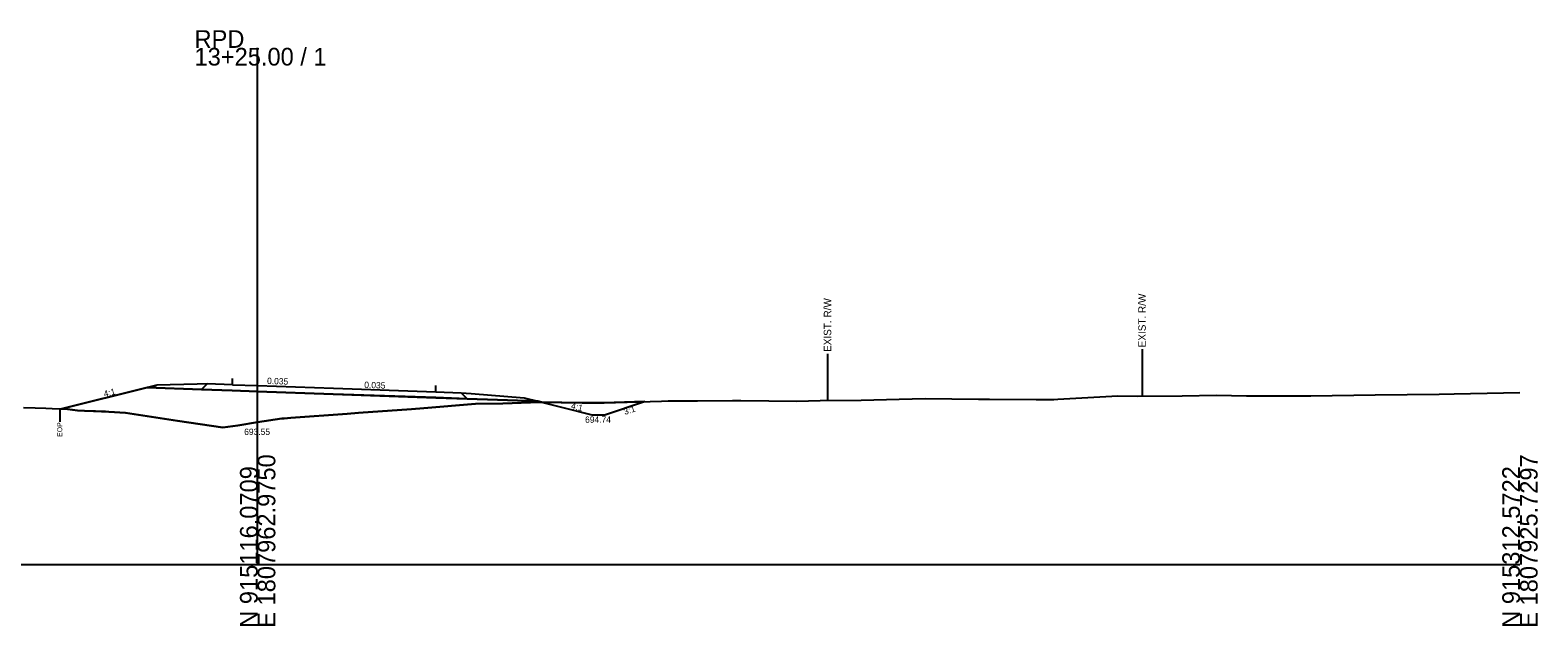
# Model space of a CAD drawing. Extents: x -26 to 403, y -10 to 8517.
# Drawn here: x 164 to 402.8, y 6490.3 to 6584.7 of the extents above; entities that cross this region are included whole.
import ezdxf

# ---------------------------------------------------------------- set-up
doc = ezdxf.new("R2010")
doc.units = 0
for name, color, linetype in [('Exist Cross Section Cell', 7, 'Continuous'), ('Exist XS Center Line Elevation Label', 7, 'Continuous'), ('Exist XS Ground Line', 7, 'Continuous'), ('Old_Level_10', 7, 'Continuous'), ('Prop XS Ditch Slope Text', 7, 'Continuous'), ('Prop XS Ditch Standard Text', 7, 'Continuous'), ('Prop XS Earthwork Shape', 7, 'Continuous'), ('Prop XS EOT Tick Mark', 7, 'Continuous'), ('Prop XS Finish Grade', 7, 'Continuous'), ('Prop XS Finish Grade Earthwork', 7, 'Continuous'), ('Prop XS Finish Grade Paved Shoulder', 7, 'Continuous'), ('Prop XS Finish Grade Pavement', 7, 'Continuous'), ('Prop XS Hydro Fill Slope Data', 7, 'Continuous'), ('Prop XS Pvmt Edge Slope', 7, 'Continuous'), ('Prop XS SE Text', 7, 'Continuous'), ('Prop XS Side Slope Text', 7, 'Continuous'), ('Prop XS Subgrade Earthwork', 7, 'Continuous')]:
    doc.layers.add(name, color=color, linetype=linetype)

msp = doc.modelspace()

# ---------------------------------------------------------------- linework, layer by layer
at = {"layer": 'Exist Cross Section Cell'}
for p, q in [((200, 6500), (200, 6581.88)), ((0, 6500), (200, 6500)), ((200, 6500), (400, 6500))]:
    msp.add_line(p, q, dxfattribs=at)
at = {"layer": 'Exist XS Ground Line'}
msp.add_lwpolyline([(162.89, 6524.9), (164.77, 6524.84), (166.43, 6524.77), (167.42, 6524.74), (168.64, 6524.7), (169.09, 6524.68), (169.85, 6524.61), (171.45, 6524.45), (172.58, 6524.39), (174.01, 6524.32), (174.32, 6524.3), (175.24, 6524.26), (175.91, 6524.24), (176.42, 6524.2), (179.08, 6524.06), (187.3, 6522.77), (194.48, 6521.72), (196.84, 6522.05), (200, 6522.55), (203.83, 6523.15), (204.18, 6523.15), (205.26, 6523.27), (214.18, 6523.91), (215.98, 6524.04), (224.36, 6524.62), (226.32, 6524.8), (234.53, 6525.48), (238.87, 6525.53), (244.71, 6525.75), (251.43, 6525.64), (254.89, 6525.64), (263.99, 6525.91), (265.07, 6525.95), (269.67, 6525.96), (275.25, 6526.03), (276.55, 6525.99), (285.42, 6525.92), (289.11, 6525.99), (295.6, 6526.07), (301.67, 6526.21), (305.78, 6526.32), (314.22, 6526.21), (315.96, 6526.21), (323.37, 6526.18), (326.14, 6526.18), (326.78, 6526.2), (336.31, 6526.75), (339.34, 6526.72), (346.49, 6526.76), (351.9, 6526.85), (356.67, 6526.77), (364.46, 6526.74), (366.85, 6526.73), (377.07, 6526.89), (387.2, 6527.01), (389.57, 6527.06), (397.38, 6527.22), (400, 6527.29)], dxfattribs=at)
at = {"layer": 'Old_Level_10'}
for p, q in [((340.13, 6534.13), (340.13, 6526.73)), ((290.29, 6533.41), (290.29, 6526)), ((168.64, 6524.7), (168.64, 6522.65))]:
    msp.add_line(p, q, dxfattribs=at)
at = {"layer": 'Prop XS Earthwork Shape'}
for points in [[(228.21, 6526.46), (233.18, 6526.29), (244.4, 6525.89), (244.99, 6525.75), (244.71, 6525.75), (238.87, 6525.53), (234.53, 6525.48), (226.32, 6524.8), (224.36, 6524.62), (215.98, 6524.04), (214.18, 6523.91), (205.26, 6523.27), (204.18, 6523.15), (203.83, 6523.15), (200, 6522.55), (196.84, 6522.05), (194.48, 6521.72), (187.3, 6522.77), (179.08, 6524.06), (176.42, 6524.2), (175.91, 6524.24), (175.24, 6524.26), (174.32, 6524.3), (174.01, 6524.32), (172.58, 6524.39), (171.45, 6524.45), (169.85, 6524.61), (169.09, 6524.68), (168.93, 6524.68), (182.47, 6528.07), (191.11, 6527.76), (195.98, 6527.59), (199.98, 6527.45), (211.98, 6527.03)], [(182.47, 6528.07), (168.93, 6524.68), (169.09, 6524.68), (169.85, 6524.61), (171.45, 6524.45), (172.58, 6524.39), (174.01, 6524.32), (174.32, 6524.3), (175.24, 6524.26), (175.91, 6524.24), (176.42, 6524.2), (179.08, 6524.06), (187.3, 6522.77), (194.48, 6521.72), (196.84, 6522.05), (200, 6522.55), (203.83, 6523.15), (204.18, 6523.15), (205.26, 6523.27), (214.18, 6523.91), (215.98, 6524.04), (224.36, 6524.62), (226.32, 6524.8), (234.53, 6525.48), (238.87, 6525.53), (244.71, 6525.75), (244.99, 6525.75), (244.4, 6525.89), (233.18, 6526.29), (228.21, 6526.46), (211.98, 6527.03), (199.98, 6527.45), (195.98, 6527.59), (191.11, 6527.76)], [(244.99, 6525.75), (253.02, 6523.74), (255.03, 6523.74), (261.29, 6525.83), (254.89, 6525.64), (251.43, 6525.64)]]:
    msp.add_lwpolyline(points, close=True, dxfattribs=at)
at = {"layer": 'Prop XS EOT Tick Mark'}
for p, q in [((196, 6528.5), (196, 6529.5)), ((228.22, 6527.37), (228.22, 6528.37))]:
    msp.add_line(p, q, dxfattribs=at)
at = {"layer": 'Prop XS Finish Grade'}
for p, q in [((182.47, 6528.05), (184, 6528.44)), ((190.43, 6528.6), (184, 6528.44)), ((192, 6528.64), (190.43, 6528.6)), ((232.22, 6527.23), (233.82, 6527.1)), ((233.82, 6527.1), (242.22, 6526.43)), ((242.22, 6526.43), (244.4, 6525.88))]:
    msp.add_line(p, q, dxfattribs=at)
at = {"layer": 'Prop XS Finish Grade Earthwork'}
for p, q in [((182.47, 6528.05), (168.97, 6524.68)), ((244.4, 6525.88), (252.97, 6523.74)), ((254.97, 6523.74), (261.23, 6525.83)), ((252.97, 6523.74), (254.97, 6523.74))]:
    msp.add_line(p, q, dxfattribs=at)
at = {"layer": 'Prop XS Finish Grade Paved Shoulder'}
for p, q in [((196, 6528.5), (192, 6528.64)), ((228.22, 6527.37), (232.22, 6527.23))]:
    msp.add_line(p, q, dxfattribs=at)
at = {"layer": 'Prop XS Finish Grade Pavement'}
for p, q in [((196, 6528.5), (200, 6528.36)), ((200, 6528.36), (212, 6527.94)), ((212, 6527.94), (228.22, 6527.37))]:
    msp.add_line(p, q, dxfattribs=at)
at = {"layer": 'Prop XS Hydro Fill Slope Data'}
msp.add_line((184, 6528.44), (168.98, 6524.68), dxfattribs=at)
at = {"layer": 'Prop XS Pvmt Edge Slope'}
for p, q in [((192, 6528.64), (191.11, 6527.75)), ((232.22, 6527.23), (233.18, 6526.28))]:
    msp.add_line(p, q, dxfattribs=at)
at = {"layer": 'Prop XS Subgrade Earthwork'}
for p, q in [((191.11, 6527.75), (182.47, 6528.05)), ((195.98, 6527.58), (191.11, 6527.75)), ((195.98, 6527.58), (199.98, 6527.44)), ((199.98, 6527.44), (211.98, 6527.02)), ((211.98, 6527.02), (228.21, 6526.45)), ((228.21, 6526.45), (233.18, 6526.28)), ((233.18, 6526.28), (244.4, 6525.88))]:
    msp.add_line(p, q, dxfattribs=at)

# ---------------------------------------------------------------- texts
at = {"layer": 'Exist Cross Section Cell'}
for s, p in [('RPD', (190, 6581.88)), ('13+25.00 / 1', (190, 6579.08))]:
    msp.add_text(s, height=2.8, dxfattribs=at).set_placement(p)
for s, p in [('E 1807962.9750', (202.8, 6490)), ('E 1807925.7297', (402.8, 6490)), ('N 915116.0709', (200, 6490)), ('N 915312.5722', (400, 6490))]:
    msp.add_text(s, height=2.8, rotation=90, dxfattribs=at).set_placement(p)
at = {"layer": 'Exist XS Center Line Elevation Label'}
msp.add_text('693.55', height=1, dxfattribs=at).set_placement((197.87, 6520.55))
at = {"layer": 'Old_Level_10'}
for s, height, rotation, p in [('EXIST. R/W', 1.181, 90, (290.88, 6533.71)), ('EXIST. R/W', 1.181, 90, (340.72, 6534.43)), ('3:1', 1, 18.4349, (258.19, 6523.71)), ('EOP', 0.787, 90, (169.04, 6520.25))]:
    msp.add_text(s, height=height, rotation=rotation, dxfattribs=at).set_placement(p)
at = {"layer": 'Prop XS Ditch Slope Text'}
msp.add_text('4:1', height=1, rotation=345.9638, dxfattribs=at).set_placement((249.58, 6524.74))
at = {"layer": 'Prop XS Ditch Standard Text'}
msp.add_text('694.74', height=1, dxfattribs=at).set_placement((251.88, 6522.48))
at = {"layer": 'Prop XS SE Text'}
for p in [(201.48, 6528.63), (216.88, 6528)]:
    msp.add_text('0.035', height=1, rotation=357.9897, dxfattribs=at).set_placement(p)
at = {"layer": 'Prop XS Side Slope Text'}
msp.add_text('4:1', height=1, rotation=14.0362, dxfattribs=at).set_placement((175.74, 6526.55))

doc.saveas('drawing.dxf')
